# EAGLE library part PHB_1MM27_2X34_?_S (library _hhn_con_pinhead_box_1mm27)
Pin Header Box-Type, 1.27mm/0.5"/50mil Pitch, 2x34 Circuits, single gates in schematic Note: see library description for an important note about THT-version
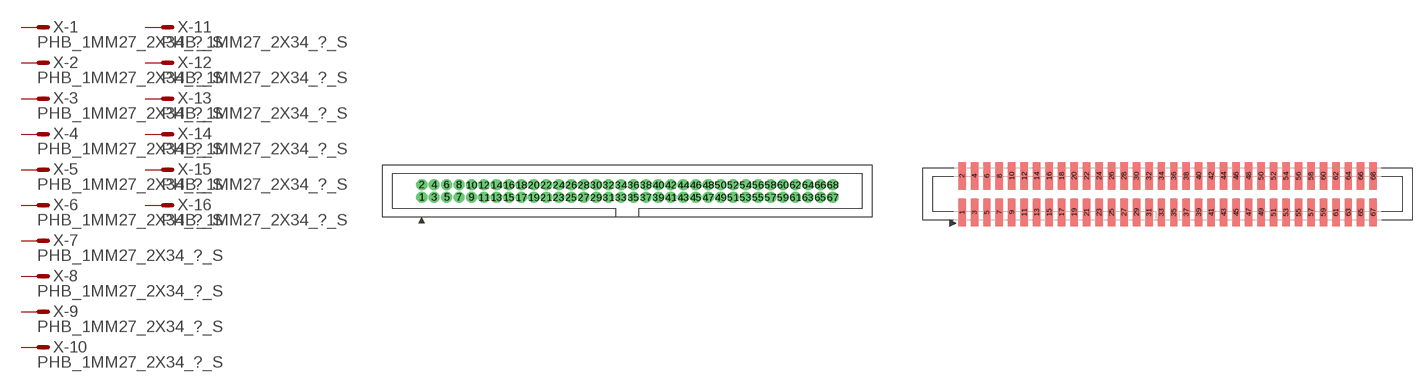
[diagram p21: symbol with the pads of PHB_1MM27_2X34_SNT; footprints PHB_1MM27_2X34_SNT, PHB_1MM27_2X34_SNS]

Designator prefix X; gates -1=M -2=M -3=M -4=M -5=M -6=M -7=M -8=M -9=M -10=M -11=M -12=M -13=M -14=M -15=M -16=M -17=M -18=M -19=M -20=M -21=M -22=M -23=M -24=M -25=M -26=M -27=M -28=M -29=M -30=M -31=M -32=M -33=M -34=M -35=M -36=M -37=M -38=M -39=M -40=M -41=M -42=M -43=M -44=M -45=M -46=M -47=M -48=M -49=M -50=M -51=M -52=M -53=M -54=M -55=M -56=M -57=M -58=M -59=M -60=M -61=M -62=M -63=M -64=M -65=M -66=M -67=M -68=M

## PHB_1MM27_2X34_SNT_S  [PHB_1MM27_2X34_SNT]
1  -1:S  pas
2  -2:S  pas
3  -3:S  pas
4  -4:S  pas
5  -5:S  pas
6  -6:S  pas
7  -7:S  pas
8  -8:S  pas
9  -9:S  pas
10  -10:S  pas
11  -11:S  pas
12  -12:S  pas
13  -13:S  pas
14  -14:S  pas
15  -15:S  pas
16  -16:S  pas
17  -17:S  pas
18  -18:S  pas
19  -19:S  pas
20  -20:S  pas
21  -21:S  pas
22  -22:S  pas
23  -23:S  pas
24  -24:S  pas
25  -25:S  pas
26  -26:S  pas
27  -27:S  pas
28  -28:S  pas
29  -29:S  pas
30  -30:S  pas
31  -31:S  pas
32  -32:S  pas
33  -33:S  pas
34  -34:S  pas
35  -35:S  pas
36  -36:S  pas
37  -37:S  pas
38  -38:S  pas
39  -39:S  pas
40  -40:S  pas
41  -41:S  pas
42  -42:S  pas
43  -43:S  pas
44  -44:S  pas
45  -45:S  pas
46  -46:S  pas
47  -47:S  pas
48  -48:S  pas
49  -49:S  pas
50  -50:S  pas
51  -51:S  pas
52  -52:S  pas
53  -53:S  pas
54  -54:S  pas
55  -55:S  pas
56  -56:S  pas
57  -57:S  pas
58  -58:S  pas
59  -59:S  pas
60  -60:S  pas
61  -61:S  pas
62  -62:S  pas
63  -63:S  pas
64  -64:S  pas
65  -65:S  pas
66  -66:S  pas
67  -67:S  pas
68  -68:S  pas

## PHB_1MM27_2X34_SNS_S  [PHB_1MM27_2X34_SNS]
Pads as for PHB_1MM27_2X34_SNT

## Footprint PHB_1MM27_2X34_SNT (pad centres in mm)
Pin Header Box-Type, 1.27mm Pitch, 2x34 circuits, Straight, No Locking, THT Important Note: Diameter in this lbr is set to a specific value (NOT 'auto' = 0), this is ignored by actual eagle versions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
drill 0.65 pad 1 round: 1 -20.955,-0.635; 2 -20.955,0.635; 3 -19.685,-0.635; 4 -19.685,0.635; 5 -18.415,-0.635; 6 -18.415,0.635; 7 -17.145,-0.635; 8 -17.145,0.635; 9 -15.875,-0.635; 10 -15.875,0.635; 11 -14.605,-0.635; 12 -14.605,0.635; 13 -13.335,-0.635; 14 -13.335,0.635; 15 -12.065,-0.635; 16 -12.065,0.635; 17 -10.795,-0.635; 18 -10.795,0.635; 19 -9.525,-0.635; 20 -9.525,0.635; 21 -8.255,-0.635; 22 -8.255,0.635; 23 -6.985,-0.635; 24 -6.985,0.635; 25 -5.715,-0.635; 26 -5.715,0.635; 27 -4.445,-0.635; 28 -4.445,0.635; 29 -3.175,-0.635; 30 -3.175,0.635; 31 -1.905,-0.635; 32 -1.905,0.635; 33 -0.635,-0.635; 34 -0.635,0.635; 35 0.635,-0.635; 36 0.635,0.635; 37 1.905,-0.635; 38 1.905,0.635; 39 3.175,-0.635; 40 3.175,0.635; 41 4.445,-0.635; 42 4.445,0.635; 43 5.715,-0.635; 44 5.715,0.635; 45 6.985,-0.635; 46 6.985,0.635; 47 8.255,-0.635; 48 8.255,0.635; 49 9.525,-0.635; 50 9.525,0.635; 51 10.795,-0.635; 52 10.795,0.635; 53 12.065,-0.635; 54 12.065,0.635; 55 13.335,-0.635; 56 13.335,0.635; 57 14.605,-0.635; 58 14.605,0.635; 59 15.875,-0.635; 60 15.875,0.635; 61 17.145,-0.635; 62 17.145,0.635; 63 18.415,-0.635; 64 18.415,0.635; 65 19.685,-0.635; 66 19.685,0.635; 67 20.955,-0.635; 68 20.955,0.635

## Footprint PHB_1MM27_2X34_SNS (pad centres in mm)
Pin Header Box-Type, 1.27mm Pitch, 2x34 circuits, Straight, No Locking, SMT
smd 0.76 x 2.8: 1 -20.955,-1.85; 2 -20.955,1.85; 3 -19.685,-1.85; 4 -19.685,1.85; 5 -18.415,-1.85; 6 -18.415,1.85; 7 -17.145,-1.85; 8 -17.145,1.85; 9 -15.875,-1.85; 10 -15.875,1.85; 11 -14.605,-1.85; 12 -14.605,1.85; 13 -13.335,-1.85; 14 -13.335,1.85; 15 -12.065,-1.85; 16 -12.065,1.85; 17 -10.795,-1.85; 18 -10.795,1.85; 19 -9.525,-1.85; 20 -9.525,1.85; 21 -8.255,-1.85; 22 -8.255,1.85; 23 -6.985,-1.85; 24 -6.985,1.85; 25 -5.715,-1.85; 26 -5.715,1.85; 27 -4.445,-1.85; 28 -4.445,1.85; 29 -3.175,-1.85; 30 -3.175,1.85; 31 -1.905,-1.85; 32 -1.905,1.85; 33 -0.635,-1.85; 34 -0.635,1.85; 35 0.635,-1.85; 36 0.635,1.85; 37 1.905,-1.85; 38 1.905,1.85; 39 3.175,-1.85; 40 3.175,1.85; 41 4.445,-1.85; 42 4.445,1.85; 43 5.715,-1.85; 44 5.715,1.85; 45 6.985,-1.85; 46 6.985,1.85; 47 8.255,-1.85; 48 8.255,1.85; 49 9.525,-1.85; 50 9.525,1.85; 51 10.795,-1.85; 52 10.795,1.85; 53 12.065,-1.85; 54 12.065,1.85; 55 13.335,-1.85; 56 13.335,1.85; 57 14.605,-1.85; 58 14.605,1.85; 59 15.875,-1.85; 60 15.875,1.85; 61 17.145,-1.85; 62 17.145,1.85; 63 18.415,-1.85; 64 18.415,1.85; 65 19.685,-1.85; 66 19.685,1.85; 67 20.955,-1.85; 68 20.955,1.85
